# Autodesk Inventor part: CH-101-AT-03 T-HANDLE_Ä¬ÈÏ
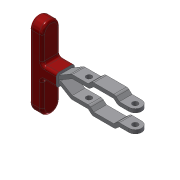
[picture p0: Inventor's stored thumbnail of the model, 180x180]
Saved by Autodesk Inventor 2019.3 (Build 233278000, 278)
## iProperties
Created: 2010-06
Part Number: CH-101-AT-03 T-HANDLE_Ä¬ÈÏ
Material: Ogólny
Document SubType Name: Modeling
Designer: CADENGINEERING4
Density: 1 g/cm^3
Appearance: Domyślna
Author: CADENGINEERING4
Revision Number: ÈÎºÎ
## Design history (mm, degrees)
feature "NONE"
node "Bryła1"
